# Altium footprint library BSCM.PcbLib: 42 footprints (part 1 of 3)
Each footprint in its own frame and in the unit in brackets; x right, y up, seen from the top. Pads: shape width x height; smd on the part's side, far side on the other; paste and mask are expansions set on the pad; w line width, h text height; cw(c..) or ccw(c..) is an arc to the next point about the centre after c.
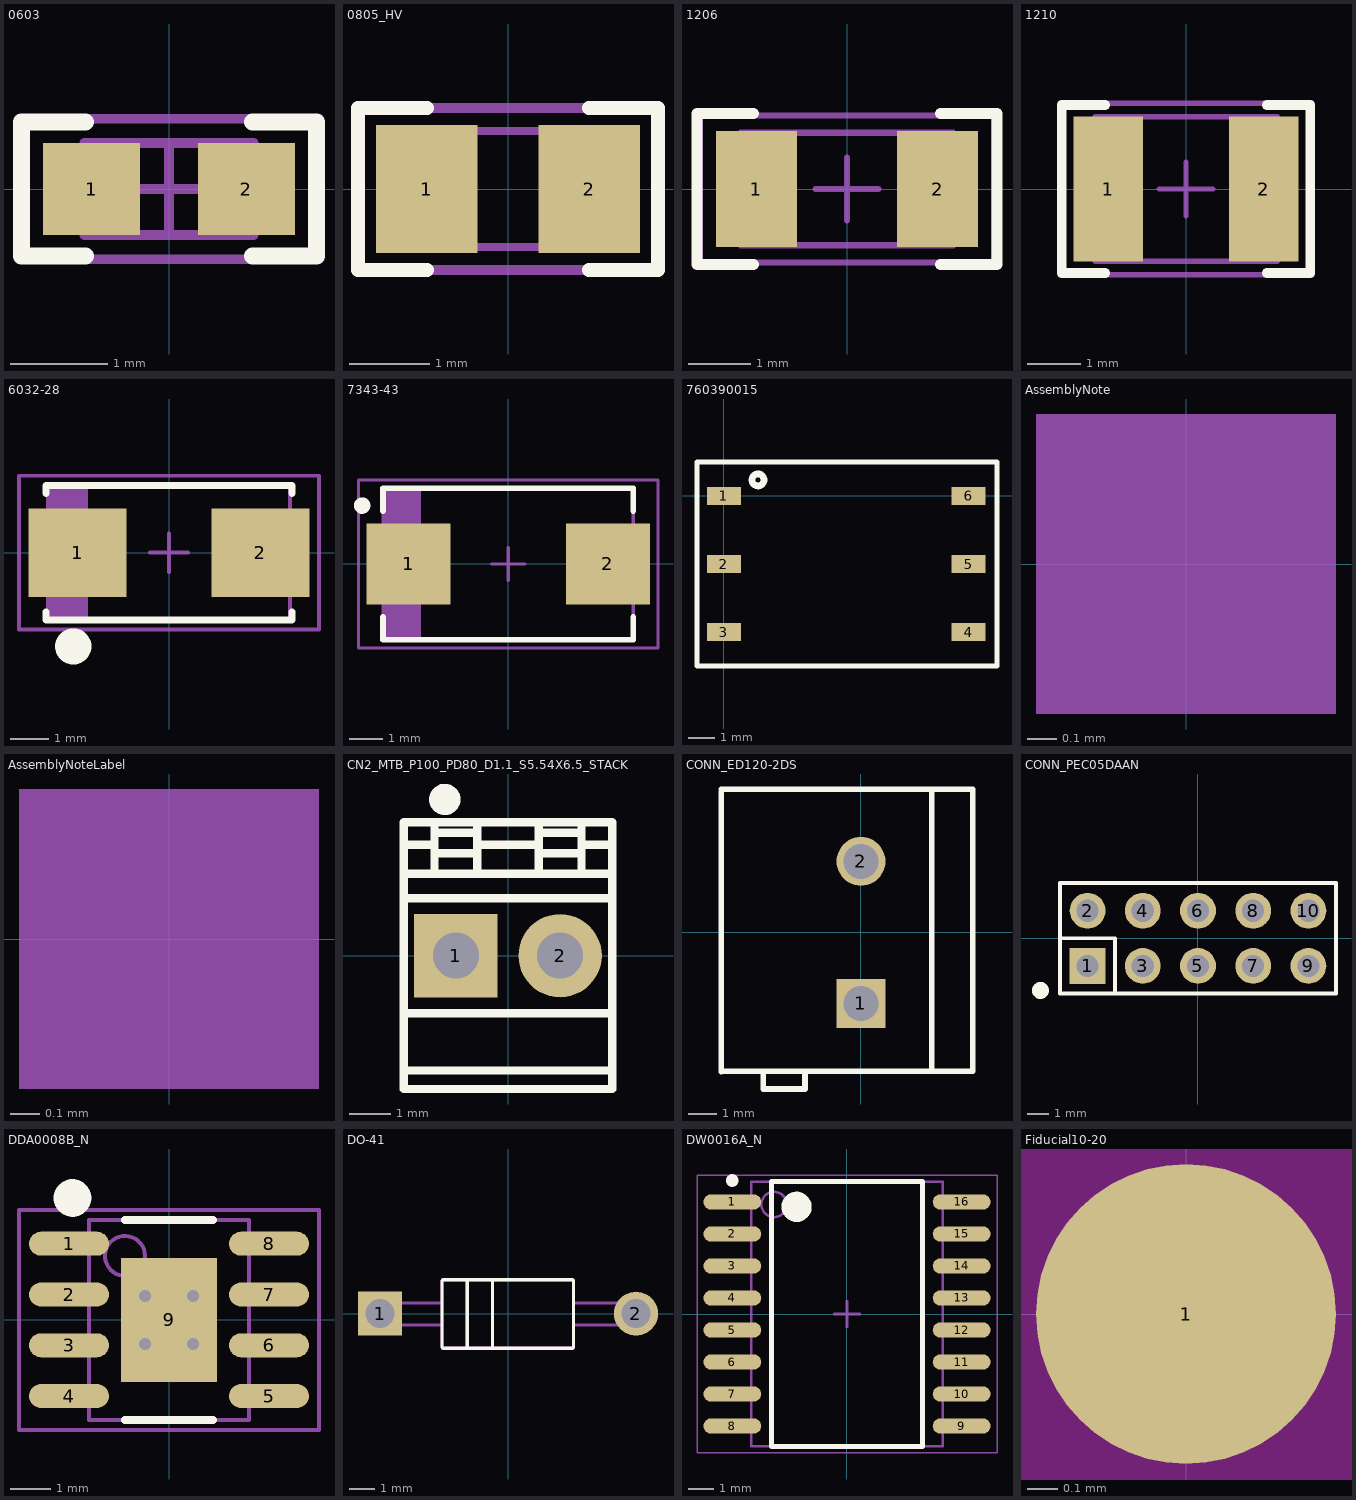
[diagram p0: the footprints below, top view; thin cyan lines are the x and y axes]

## 0603 [mm] "0603 from SM-752 data"
height 0.85
pads (2):
  rect 1x0.95 smd: 1(-0.8,0) 2(0.8,0)
Top Overlay:
  lines w0.178: -0.864,-0.691 -1.524,-0.691 -1.524,0.693 -0.864,0.693 ; 0.864,-0.691 1.524,-0.691 1.524,0.693 0.864,0.693
Mechanical 5:
  lines w0.1: -1.55,-0.725 1.55,-0.725 1.55,0.725 -1.55,0.725 -1.55,-0.725
  text ".Designator" at -1.397,-0.381 h0.76
Mechanical 13:
  lines w0.1: -0.55,-0.475 -0.55,0.475 ; 0.55,-0.475 0.55,0.475 ; -0.875,-0.475 -0.875,0.475 0.875,0.475 0.875,-0.475 -0.875,-0.475
Mechanical 15:
  lines w0.1: -0.475,0 0.475,0 ; 0,-0.475 0,0.475 ; -1.55,-0.725 -1.55,0.725 1.55,0.725 1.55,-0.725 -1.55,-0.725
3D body: height 0.85, standoff 0, extent 0.551,-0.474 0.874,0.474
3D body: height 0.85, standoff 0, extent -0.549,-0.474 0.549,0.474
3D body: height 0.85, standoff 0, extent -0.874,-0.474 -0.551,0.474

## 0805_HV [mil] "0805 with 30mil clearance between pads"
height 43.31
pads (2):
  rect 50x63 smd: 1(-40,0) 2(40,0)
Top Overlay:
  lines w7: -40,-40 -74,-40 -74,0 -74,40 -40,40 ; 40,-40 74,-40 74,0 74,40 40,40
Mechanical 5:
  lines w5: -74,-40 -74,40 74,40 74,-40 -74,-40
  text ".Designator" at 30,21 h40
Mechanical 13:
  lines w3.94: -25.59,-28.54 -25.59,28.54 ; 25.59,-28.54 25.59,28.54 ; -43.31,-28.54 43.31,-28.54 43.31,28.54 -43.31,28.54 -43.31,-28.54
3D body: height 43.31, standoff 0, extent -43.29,-28.52 -25.61,28.52
3D body: height 43.31, standoff 0, extent -25.57,-28.52 25.57,28.52
3D body: height 43.31, standoff 0, extent 25.61,-28.52 43.29,28.52

## 1206 [mm] "1206 from SM-752 data"
height 1.35
pads (2):
  rect 1.3x1.85 smd: 1(-1.45,0) 2(1.45,0)
Top Overlay:
  lines w0.178: -1.5,-1.21 -2.4,-1.21 -2.4,1.21 -1.5,1.21 ; 1.5,-1.21 2.4,-1.21 2.4,1.21 1.5,1.21
Mechanical 5:
  lines w0.1: -1.7,-0.9 1.7,-0.9 1.7,0.9 -1.7,0.9 -1.7,-0.9
  text ".Designator" at -1.475,-0.4 h0.81
Mechanical 13:
  lines w0.1: -1.2,-0.9 -1.2,0.9 ; 1.2,-0.9 1.2,0.9 ; -1.7,-0.9 1.7,-0.9 1.7,0.9 -1.7,0.9 -1.7,-0.9
Mechanical 15:
  lines w0.1: -0.5,0 0.5,0 ; 0,-0.5 0,0.5 ; -2.35,-1.175 2.35,-1.175 2.35,1.175 -2.35,1.175 -2.35,-1.175
3D body: height 1.35, standoff 0, extent -1.699,-0.899 -1.201,0.899
3D body: height 1.35, standoff 0, extent -1.199,-0.899 1.199,0.899
3D body: height 1.35, standoff 0, extent 1.201,-0.899 1.699,0.899

## 1210 [mm] "1210 from SM-752 data"
height 1.35
pads (2):
  rect 1.3x2.7 smd: 1(-1.45,0) 2(1.45,0)
Top Overlay:
  lines w0.178: -1.511,-1.568 -2.316,-1.568 -2.316,1.568 -1.511,1.568 ; 1.511,-1.568 2.316,-1.568 2.316,1.568 1.511,1.568
Mechanical 5:
  lines w0.1: -1.7,-1.35 1.7,-1.35 1.7,1.35 -1.7,1.35 -1.7,-1.35
  text ".Designator" at -0.864,-0.33 h1.02
Mechanical 13:
  lines w0.1: -1.2,-1.35 -1.2,1.35 ; 1.2,-1.35 1.2,1.35 ; -1.7,-1.35 -1.7,1.35 1.7,1.35 1.7,-1.35 -1.7,-1.35
Mechanical 15:
  lines w0.1: -0.5,0 0.5,0 ; 0,-0.5 0,0.5 ; -2.35,-1.6 -2.35,1.6 2.35,1.6 2.35,-1.6 -2.35,-1.6
3D body: height 1.35, standoff 0, extent -1.699,-1.349 -1.201,1.349
3D body: height 1.35, standoff 0, extent -1.199,-1.349 1.199,1.349
3D body: height 1.35, standoff 0, extent 1.201,-1.349 1.699,1.349

## 6032-28 [mm] "Medium Density IPC based on Vishay Sprague 293D datasheet."
height 2.8
pads (2):
  rect 2.55x2.3 smd: 1(-2.375,0) 2(2.375,0)
Top Overlay:
  circle w0.635: c-2.489,-2.438 r0.152
  lines w0.178: -3.2,-1.539 -3.2,-1.75 3.2,-1.75 3.2,-1.539 ; -3.2,1.539 -3.2,1.75 3.2,1.75 3.2,1.539
Mechanical 5:
  rectangle: -3.15,-1.75 -2.15,1.75
  lines w0.1: -2.15,-1.75 -2.15,1.75 ; -3.15,-1.75 3.15,-1.75 3.15,1.75 -3.15,1.75 -3.15,-1.75
  text ".Designator" at 0.813,0.559 h1.02
Mechanical 15:
  lines w0.1: -0.5,0 0.5,0 ; 0,-0.5 0,0.5 ; -3.9,-2 -3.9,2 3.9,2 3.9,-2 -3.9,-2
3D body: height 2.8, standoff 2.8, extent -3.149,-1.749 -2.151,1.749
3D body: height 2.8, standoff 0, extent -3.15,-1.75 3.15,1.75

## 7343-43 [mm] "Medium density IPC based on Kemet T495 series"
height 4.3
pads (2):
  rect 2.55x2.45 smd: 1(-3.025,0) 2(3.025,0)
Top Overlay:
  circle w0.25: c-4.439,1.775 r0.125
  lines w0.178: -3.8,-1.614 -3.8,-2.3 3.8,-2.3 3.8,-1.614 ; -3.8,1.614 -3.8,2.3 3.8,2.3 3.8,1.614
Mechanical 5:
  rectangle: -3.8,-2.3 -2.7,2.3
  lines w0.1: -2.7,-2.3 -2.7,2.3 ; -3.8,-2.3 3.8,-2.3 3.8,2.3 -3.8,2.3 -3.8,-2.3
  text ".Designator" at -1.194,-0.457 h1.02
Mechanical 15:
  lines w0.1: -0.5,0 0.5,0 ; 0,-0.5 0,0.5 ; -4.55,-2.55 4.55,-2.55 4.55,2.55 -4.55,2.55 -4.55,-2.55
3D body: height 4.3, standoff 0, extent -3.8,-2.3 3.8,2.3
3D body: height 4.3, standoff 4.3, extent -3.799,-2.299 -2.701,2.299

## 760390015 [mm]
pads (6):
  rect 1.27x0.66 smd: 1(0,0) 2(0,-2.54) 3(0,-5.08) 4(9.14,-5.08) 5(9.14,-2.54) 6(9.14,0)
Top Overlay:
  circle w0.254: c1.276,0.6 r0.224
  lines w0.2: -1,-6.35 -1,1.27 10.2,1.27 10.2,-6.35 -1,-6.35
3D body: height 4.2, standoff 0.2, extent -1,-6.4 10.2,1.2

## AssemblyNote [mil] "Assembly Note"
Mechanical 5:
  rectangle: -20,-20 20,20
  text ".Designator" at -165,-20 h40
  text ".Comment" at 45,-20 h40

## AssemblyNoteLabel [mil] "Assembly Note for PCB Labels"
Mechanical 5:
  rectangle: -20,-20 20,20
  text ".Designator" at -165,-20 h40
  text "Install label in silkscreened box after final wash.  Text shall be 8 pt font.  Text shall be per the Label Table in the PDF schematic." at 45,-20 h40

## CN2_MTB_P100_PD80_D1.1_S5.54X6.5_STACK [mil]
height 400
pads (2):
  rect 80x80 / inner round 80 / far side rect 80x80 hole 44: 1(-50,0)
  round 80 hole 44: 2(50,0)
Top Overlay:
  circle w10: c-60.63,149.95 r10
  circle w10: c-60.63,149.95 r5
  lines w8: -100,-110.24 100,-110.24 ; -100,-55.12 100,-55.12 ; -100,55.12 100,55.12 ; -100,78.74 100,78.74 ; -100,106.3 -70.87,106.3 ; -70.47,78.74 -70.47,127.95 ; -70.47,98.43 -31.5,98.43 ; -70.47,118.11 -31.5,118.11 ; -29.53,78.74 -29.53,127.95 ; -27.56,106.3 27.56,106.3 ; 29.53,78.74 29.53,127.95 ; 31.5,98.43 66.93,98.43 ; 31.5,118.11 66.93,118.11 ; 70.47,78.74 70.47,127.95 ; 70.87,106.3 100,106.3 ; -100,-127.95 100,-127.95 100,127.95 -100,127.95 -100,-127.95

## CONN_ED120-2DS [mm] "ONSHORE"
height 13
pads (2):
  rect 1.75x1.75 hole 1.25: 1(0,-2.54)
  round 1.75 hole 1.25: 2(0,2.54)
Top Overlay:
  lines w0.2: -5,-4.985 -5,5.015 ; -5,-4.96 4,-4.96 ; -5,5.115 4,5.115 4,-4.885 ; -3.5,-4.96 -3.5,-5.6 -2,-5.6 -2,-4.96 ; 2.525,-4.95 2.525,5.05
Mechanical 5:
  lines w0.1: -5,-4.96 4,-4.96 ; -5,-4.885 -5,5.115 4,5.115 4,-4.885 ; -3.5,-4.96 -3.5,-5.6 -2,-5.6 -2,-4.96 ; 2.525,-4.875 2.525,5.125
  text ".Designator" at -2.75,-0.4 h1.02
3D body: height 13, standoff 0, extent -3.5,-5.6 -2,-4.925
3D body: height 5.7, standoff 4.3, extent -0.875,-3.204 4.125,-1.81
3D body: height 5.7, standoff 4.3, extent -0.85,1.846 4.15,3.24
3D body: height 13.1, standoff -2.5, extent -0.496,2.041 0.5,3.039
3D body: height 13.1, standoff -2.5, extent -0.496,-3.039 0.5,-2.041
3D body: height 13, standoff 0, extent -5,-4.985 4,5.115

## CONN_PEC05DAAN [mm] "SULLINS"
height 8.382
pads (10):
  rect 1.65x1.65 hole 1.016 mask+0: 1(-5.08,-1.27)
  round 1.65 hole 1.016 mask+0: 2(-5.08,1.27) 3(-2.54,-1.27) 4(-2.54,1.27) 5(0,-1.27) 6(0,1.27) 7(2.54,-1.27) 8(2.54,1.27) 9(5.08,-1.27) 10(5.08,1.27)
Top Overlay:
  circle w0.381: c-7.25,-2.4 r0.203
  lines w0.178: -6.35,0 -3.81,0 -3.81,-2.54 ; -6.35,-2.54 6.35,-2.54 6.35,2.54 -6.35,2.54 -6.35,-2.54
Mechanical 5:
  rectangle: -5.588,-1.778 -4.572,-0.762
  lines w0.076: -6.35,-2.54 6.35,-2.54 6.35,2.54 -6.35,2.54 -6.35,-2.54
  lines w0.127: -6.35,-2.54 -6.35,2.54 6.35,2.54 6.35,-2.54 -6.35,-2.54
  text ".Designator" at -1.778,-0.508 h1.02
3D body: height 8.38, standoff -3.05, extent -5.397,-1.587 -4.762,-0.952
3D body: height 8.38, standoff -3.05, extent -5.397,0.953 -4.762,1.588
3D body: height 8.38, standoff -3.05, extent -2.857,0.953 -2.222,1.588
3D body: height 8.38, standoff -3.05, extent -2.857,-1.587 -2.222,-0.952
3D body: height 8.38, standoff -3.05, extent -0.317,-1.587 0.318,-0.952
3D body: height 8.38, standoff -3.05, extent -0.317,0.953 0.318,1.588
3D body: height 8.38, standoff -3.05, extent 2.223,-1.587 2.858,-0.952
3D body: height 8.38, standoff -3.05, extent 2.223,0.953 2.858,1.588
3D body: height 8.38, standoff -3.05, extent 4.763,-1.587 5.398,-0.952
3D body: height 8.38, standoff -3.05, extent 4.763,0.953 5.398,1.588
3D body: height 2.54, standoff 0, extent -6.349,-2.539 6.349,2.539

## DDA0008B_N [mm] "SOIC, 8-Leads, Body 4.9x3.9mm, Pitch 1.27mm, Exposed Pad, IPC Medium Density"
height 1.68
pads (9):
  oval 2x0.6 smd: 1(-2.5,1.905) 2(-2.5,0.635) 3(-2.5,-0.635) 4(-2.5,-1.905) 5(2.5,-1.905) 6(2.5,-0.635) 7(2.5,0.635) 8(2.5,1.905)
  rect 2.41x3.1 smd: 9(0,0)
via -0.6,0.6 diameter 0.66 hole 0.305
via 0.6,0.6 diameter 0.66 hole 0.305
via 0.6,-0.6 diameter 0.66 hole 0.305
via -0.6,-0.6 diameter 0.66 hole 0.305
Top Overlay:
  circle w0.635: c-2.413,3.048 r0.152
  lines w0.2: -1.1,-2.5 1.1,-2.5 ; -1.1,2.5 1.1,2.5
Mechanical 5:
  circle w0.1: c-1.1,1.6 r0.5
  lines w0.1: -2,-2.5 -2,2.5 2,2.5 2,-2.5 -2,-2.5
  text ".Designator" at -0.838,-0.483 h1.02
Mechanical 15:
  lines w0.1: -0.5,0 0.5,0 ; 0,-0.5 0,0.5 ; -3.75,-2.75 -3.75,2.75 3.75,2.75 3.75,-2.75 -3.75,-2.75
3D body: height 1.68, standoff 0.03, extent -2,-2.5 2,2.5

## DO-41 [mm] "diode"
height 3
pads (2):
  rect 1.75x1.75 hole 1.15: 1(-5.08,0)
  round 1.75 hole 1.15: 2(5.08,0)
Top Overlay:
  lines w0.127: -1.615,-1.371 -0.615,-1.371 ; -1.615,1.347 -0.615,1.347 ; -2.615,-1.322 ccw(c-2.565,-1.322) -2.565,-1.372 -1.615,-1.372 -1.615,-0.012 -1.615,1.348 -2.565,1.348 ccw(c-2.565,1.298) -2.615,1.298 -2.615,-0.012 -2.615,-1.322 ; -0.615,-1.372 2.545,-1.372 ccw(c2.545,-1.322) 2.595,-1.322 2.595,1.298 ccw(c2.545,1.298) 2.545,1.348 -0.615,1.348 -0.615,-1.372
Mechanical 5:
  lines w0.127: -2.615,-0.444 -4.09,-0.444 -5.09,-0.444 cw(c-5.09,-0.012) -5.522,-0.012 cw(c-5.09,-0.012) -5.09,0.42 -4.09,0.42 -2.615,0.42 ; -1.615,-1.371 -0.615,-1.371 ; -1.615,1.347 -0.615,1.347 ; 2.595,-0.444 4.07,-0.444 5.07,-0.444 ccw(c5.07,-0.012) 5.502,-0.012 ccw(c5.07,-0.012) 5.07,0.42 4.07,0.42 2.595,0.42 ; -2.615,-1.322 ccw(c-2.565,-1.322) -2.565,-1.372 -1.615,-1.372 -1.615,-0.012 -1.615,1.348 -2.565,1.348 ccw(c-2.565,1.298) -2.615,1.298 -2.615,-0.012 -2.615,-1.322 ; -0.615,-1.372 -0.615,1.348 2.545,1.348 cw(c2.545,1.298) 2.595,1.298 2.595,-1.322 cw(c2.545,-1.322) 2.545,-1.372 -0.615,-1.372
  text ".Designator" at -0.178,-0.254 h0.51
3D body: height 2.72, standoff -2.6, extent -5.512,-1.36 5.512,1.36

## DW0016A_N [mm] "SOIC, 16-Leads, Body 10.3x7.5mm, Pitch 1.27mm, IPC Medium Density"
height 2.64
pads (16):
  oval 2.3x0.6 smd: 1(-4.55,4.445) 2(-4.55,3.175) 3(-4.55,1.905) 4(-4.55,0.635) 5(-4.55,-0.635) 6(-4.55,-1.905) 7(-4.55,-3.175) 8(-4.55,-4.445) 9(4.55,-4.445) 10(4.55,-3.175) 11(4.55,-1.905) 12(4.55,-0.635) 13(4.55,0.635) 14(4.55,1.905) 15(4.55,3.175) 16(4.55,4.445)
Top Overlay:
  circle w0.6: c-2,4.25 r0.3
  circle w0.25: c-4.55,5.295 r0.125
  lines w0.2: -3,-5.25 3,-5.25 3,5.25 -3,5.25 -3,-5.25
Mechanical 5:
  circle w0.1: c-2.895,4.345 r0.5
  lines w0.1: -3.795,-5.245 3.795,-5.245 3.795,5.245 -3.795,5.245 -3.795,-5.245
  text ".Designator" at 1.168,0.457 h1.02
Mechanical 15:
  lines w0.05: -5.95,-5.5 5.95,-5.5 5.95,5.5 -5.95,5.5 -5.95,-5.5
  lines w0.1: -0.5,0 0.5,0 ; 0,-0.5 0,0.5
3D body: height 2.64, standoff 0.1, extent -3.795,-5.245 3.795,5.245

## Fiducial10-20 [mm]
pads (1):
  round 1 smd mask+0.5: 1(0,0)
Top Layer keep-out:
  circle w1.178: c0,0 r0.5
